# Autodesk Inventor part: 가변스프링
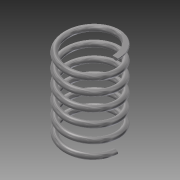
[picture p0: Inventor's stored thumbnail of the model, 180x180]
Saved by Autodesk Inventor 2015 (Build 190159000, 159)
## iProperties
Created: 2015-10
Part Number: 가변스프링
Material: Steel, Mild
Document SubType Name: Modeling
Designer: youjin22
Density: 7.85 g/cm^3
Appearance: Semi-Polished
Mass: 128.867 g
Surface Area: 133.048 cm^2
Volume: 16.4161 cm^3
Author: youjin22
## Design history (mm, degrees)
sketch "Sketch1"
  geometry: L1 (0, 0)-(-22.5, 0); L2 (-22.5, 0)-(-22.5, 73.25); L3 (-22.5, 73.25)-(0, 73.25); L4 (0, 73.25)-(0, 0); C1 r 2.5 at (-22.5, 0)
  constraints: 8 end point, 2 parallel, 1 centre point, 1 coincident, 1 horizontal, 1 perpendicular
  dimensions: "d0" = 73.25 distance between parallel lines of L1 L3 (derived); "d1" = 45 diameter of L2 L4; "d2" = 5 diameter of C1
coil "Coil1" sketch "Sketch1" pitch "d3" = 10; turns "d5" = 6; dims "d4" = 73.25 (= d0), "d6" = 0, angle "d7" = 90 deg, angle "d8" = 90 deg, "d9" = 0, "d10" = 0
sketch "Sketch2"
  geometry: L1 (20, 0)-(25, 0) reference; 1 further point
  constraints: 1 horizontal alignment
extrude "Extrusion1" cut sketch "Sketch2" stored distance "d11" = 10; taper "d12" = 0 deg
workplane "Work Plane1"
sketch "Sketch3"
  geometry: L1 (-20, 0)-(-25, 0) reference; 1 further point
  constraints: 1 horizontal alignment
extrude "Extrusion2" cut sketch "Sketch3" stored distance "d13" = 10; taper "d14" = 0 deg
body "Solid1"
node "Project Cut Edges1"
node "Project Cut Edges2"
